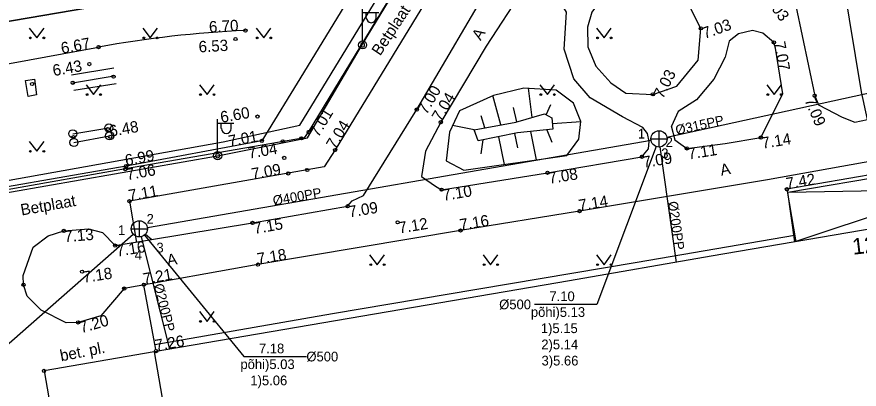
# Model space of a CAD drawing. Extents: x 473307 to 473719, y 6532843 to 6533381.
# Drawn here: x 473532 to 473584, y 6533003.3 to 6533026.3 of the extents above; entities that cross this region are included whole.
import ezdxf

# ---------------------------------------------------------------- set-up
doc = ezdxf.new("R2010")
doc.units = 0
for name, color, linetype in [('AED', 7, 'Continuous'), ('Default', 7, 'Continuous'), ('HALJASTUS', 7, 'Continuous'), ('HOONE', 7, 'Continuous'), ('HOONEDET', 7, 'Continuous'), ('KORGUS', 7, 'Continuous'), ('KPKAABEL', 7, 'Continuous'), ('MPKAABEL', 7, 'Continuous'), ('PIIR', 7, 'Continuous'), ('POST', 7, 'Continuous'), ('RAJATIS', 7, 'Continuous'), ('RELJEEF', 7, 'Continuous'), ('SKKAEV', 7, 'Continuous'), ('SKKAEV_NR', 7, 'Continuous'), ('SKTRASS', 7, 'Continuous'), ('SKTRASS_TEKST', 7, 'Continuous'), ('TEE', 7, 'Continuous')]:
    doc.layers.add(name, color=color, linetype=linetype)

# ---------------------------------------------------------------- blocks, each defined once
blk = doc.blocks.new('MURU')
at = {"layer": 'Default'}
for p, q in [((-0.93, 1.21), (0, 0)), ((0, 0), (0.89, 1.21))]:
    blk.add_line(p, q, dxfattribs=at)
for centre in [(-0.8, 0), (0.86, 0)]:
    blk.add_circle(centre, 0.11, dxfattribs=at)
blk = doc.blocks.new('PUPOST')
at = {"layer": 'Default'}
blk.add_circle((0, 0), 0.5, dxfattribs=at)
blk = doc.blocks.new('MEPOST')
at = {"layer": 'Default'}
blk.add_circle((0, 0), 0.5, dxfattribs=at)
for start, end in [(0, 180), (180, 0)]:
    blk.add_arc((0, 0), 0.25, start, end, dxfattribs=at)
blk = doc.blocks.new('VAPOST')
at = {"layer": 'Default'}
for p, q in [((0, 0.5), (0, 4.5)), ((0, 4), (2, 4)), ((0.45, 3.36), (0.45, 4)), ((1.68, 3.36), (1.68, 4))]:
    blk.add_line(p, q, dxfattribs=at)
blk.add_arc((1.07, 3.36), 0.613, 180, 0, dxfattribs=at)
blk = doc.blocks.new('KAKAEV')
at = {"layer": 'Default'}
for p, q in [((-1, 0), (1, 0)), ((0, -1), (0, 1))]:
    blk.add_line(p, q, dxfattribs=at)
blk.add_circle((0, 0), 1, dxfattribs=at)

msp = doc.modelspace()

# ---------------------------------------------------------------- linework, layer by layer
at = {"layer": 'AED'}
msp.add_lwpolyline([(473572.372, 6533059.989), (473562.796, 6533044.25), (473549.715, 6533022.819), (473547.153, 6533018.61), (473538.777, 6533017.059), (473515.614, 6533013.019), (473502.84, 6533010.765), (473486.499, 6533007.9), (473486.322, 6533008.043), (473484.734, 6533009.635), (473455.331, 6533045.745), (473429.609, 6533087.699), (473409.64, 6533128.98), (473398.626, 6533166.806)], dxfattribs=at)
at = {"layer": 'HALJASTUS'}
msp.add_lwpolyline([(473523.113, 6533015.835), (473521.816, 6533021.592), (473537.083, 6533024.398)], dxfattribs=at)
msp.add_arc((473549, 6532959.562), 65.922, 92.48527, 100.41445, dxfattribs=at)
at = {"layer": 'HOONE'}
for points in [[(473580.042, 6533012.374), (473579.602, 6533015.453), (473599.285, 6533018.774)], [(473599.285, 6533018.774), (473580.042, 6533012.374)], [(473579.602, 6533015.453), (473599.989, 6533015.81)]]:
    msp.add_lwpolyline(points, dxfattribs=at)
msp.add_lwpolyline([(473585.831, 6533013.369), (473574.881, 6533011.486), (473566.132, 6533009.962), (473540.511, 6533005.576), (473543.395, 6532988.91), (473585.455, 6532976.623), (473588.828, 6532956.753), (473587.886, 6532956.595), (473589.164, 6532949.286), (473629.221, 6532956.166), (473626.335, 6532972.834), (473619.836, 6532974.765), (473602.305, 6532979.874), (473597.625, 6532979.18), (473590.334, 6532981.418), (473586.157, 6533005.917), (473587.084, 6533006.076)], close=True, dxfattribs=at)
at = {"layer": 'HOONEDET'}
msp.add_lwpolyline([(473540.509, 6533005.59), (473533.715, 6533004.411), (473535.999, 6532991.198), (473543.379, 6532989.006)], dxfattribs=at)
at = {"layer": 'KORGUS'}
for centre in [(473574.239, 6533025.558), (473546.141, 6533025.422), (473545.529, 6533024.899), (473578.745, 6533024.687), (473537.083, 6533024.398), (473536.513, 6533023.351), (473538.004, 6533022.577), (473532.977, 6533022.124), (473535.49, 6533022.201), (473571.272, 6533021.483), (473581.265, 6533021.395), (473556.713, 6533020.545), (473546.887, 6533020.114), (473537.653, 6533019.344), (473558.193, 6533019.759), (473535.53, 6533018.837), (473537.802, 6533018.86), (473549.604, 6533018.77), (473550.041, 6533019.154), (473577.938, 6533018.813), (473547.153, 6533018.61), (473548.443, 6533018.58), (473551.671, 6533018.048), (473573.376, 6533018.143), (473548.538, 6533017.561), (473570.602, 6533017.631), (473538.726, 6533016.871), (473538.777, 6533017.059), (473549.953, 6533016.813), (473548.78, 6533016.602), (473564.78, 6533016.645), (473558.247, 6533015.597), (473579.55, 6533015.627), (473538.987, 6533014.888), (473552.448, 6533014.574), (473566.756, 6533014.277), (473555.533, 6533013.583), (473534.935, 6533013.053), (473546.585, 6533013.544), (473559.414, 6533013.077), (473538.104, 6533012.148), (473546.916, 6533010.975), (473536.058, 6533010.536), (473532.448, 6533009.73), (473538.663, 6533009.49), (473539.88, 6533009.732), (473535.82, 6533007.404), (473540.628, 6533005.633), (473533.715, 6533004.411)]:
    msp.add_circle(centre, 0.1, dxfattribs=at)
at = {"layer": 'KPKAABEL'}
msp.add_lwpolyline([(473495.73, 6532998.121), (473498.407, 6533003.379), (473503.632, 6533009.182), (473506.507, 6533009.537), (473509.619, 6533010.052), (473512.488, 6533010.976), (473514.601, 6533011.91), (473515.942, 6533013.381), (473544.763, 6533018.559), (473549.505, 6533019.588), (473569.283, 6533052.043), (473570.889, 6533054.575), (473571.863, 6533055.605), (473572.956, 6533056.611), (473574.847, 6533057.468), (473575.894, 6533057.765), (473578.381, 6533058.268)], dxfattribs=at)
at = {"layer": 'MPKAABEL'}
msp.add_lwpolyline([(473501.9, 6533010.247), (473503.599, 6533009.473), (473509.407, 6533010.303), (473514.158, 6533011.944), (473514.882, 6533012.941), (473529.573, 6533015.086), (473544.413, 6533017.683), (473549.969, 6533018.802), (473553.371, 6533024.572), (473561.183, 6533037.449), (473569.11, 6533050.338), (473570.373, 6533053.16), (473572.968, 6533056.378), (473576.022, 6533057.174), (473577.298, 6533057.025), (473577.882, 6533057.546), (473591.171, 6533059.946)], dxfattribs=at)
for points in [[(473557.128, 6533166.896), (473557.202, 6533167.153), (473557.17, 6533167.374), (473557.049, 6533167.727), (473556.952, 6533168.034), (473556.879, 6533168.251), (473556.724, 6533168.7), (473555.529, 6533172.103), (473554.018, 6533176.143), (473551.965, 6533180.794), (473542.001, 6533194.467), (473528.815, 6533203.479), (473521.877, 6533205.787), (473521.549, 6533205.862), (473521.332, 6533205.91), (473521.125, 6533205.955), (473520.94, 6533205.994), (473520.783, 6533206.026), (473520.617, 6533205.983), (473520.549, 6533205.81), (473520.512, 6533205.71), (473520.33, 6533205.301), (473520.277, 6533205.676), (473520.247, 6533205.87), (473520.186, 6533205.982), (473520.155, 6533206.063), (473520.032, 6533206.188), (473519.647, 6533206.25), (473519.297, 6533206.303), (473518.91, 6533206.37), (473518.338, 6533206.457), (473517.785, 6533206.534), (473517.113, 6533206.617), (473504.722, 6533206.361), (473489.125, 6533201.073), (473481.589, 6533195.708), (473477.331, 6533191.94), (473475.034, 6533189.807), (473474.489, 6533189.292), (473474.068, 6533188.932), (473473.832, 6533188.684), (473473.679, 6533188.468), (473473.566, 6533188.217), (473473.476, 6533188.304), (473473.306, 6533188.406), (473473.134, 6533188.531), (473472.969, 6533188.652), (473471.778, 6533189.567), (473469.957, 6533190.966), (473467.155, 6533193.119), (473463.064, 6533196.262), (473458.646, 6533199.657), (473454.573, 6533202.786), (473453.666, 6533203.482), (473453.293, 6533203.769), (473452.995, 6533203.998), (473452.474, 6533204.222), (473452.213, 6533204.228), (473451.967, 6533204.234), (473451.474, 6533204.245), (473450.255, 6533204.273), (473449.394, 6533204.293), (473448.978, 6533204.302), (473448.578, 6533204.312), (473448.301, 6533204.318), (473447.638, 6533204.311), (473446.313, 6533204.297), (473445.312, 6533204.286), (473443.932, 6533204.272), (473441.622, 6533204.247), (473436.282, 6533204.191), (473430.619, 6533203.804), (473423.016, 6533203.284), (473416.174, 6533202.8), (473411.7, 6533202.424), (473406.989, 6533202.027), (473406.298, 6533201.969), (473405.901, 6533201.936), (473405.663, 6533201.916), (473405.247, 6533201.618), (473405.511, 6533201.478), (473405.706, 6533201.471), (473405.859, 6533201.485), (473406.073, 6533201.505), (473406.3, 6533201.526), (473406.699, 6533201.563), (473407.182, 6533201.607), (473407.617, 6533201.647), (473410.794, 6533201.939), (473414.597, 6533202.289), (473416.16, 6533202.433), (473416.748, 6533202.487), (473416.992, 6533202.509), (473417.116, 6533202.479), (473417.282, 6533202.408), (473417.308, 6533202.242), (473417.347, 6533201.989), (473417.396, 6533201.677), (473417.449, 6533201.337), (473417.509, 6533200.949), (473418.04, 6533197.53), (473418.813, 6533192.552), (473421.708, 6533179.543), (473422.341, 6533175.512), (473423.507, 6533169.632), (473424, 6533167.141), (473424.184, 6533166.215), (473424.244, 6533165.909), (473424.294, 6533165.662), (473424.314, 6533165.561), (473424.105, 6533164.865), (473423.816, 6533164.809), (473423.525, 6533164.753), (473422.668, 6533164.588), (473418.846, 6533164.247), (473414.425, 6533164.061), (473411.47, 6533164.651), (473411.357, 6533164.673), (473410.881, 6533164.787), (473410.433, 6533164.888), (473409.953, 6533164.731), (473409.752, 6533164.287), (473409.631, 6533163.669), (473409.502, 6533157.703), (473410.074, 6533152.735), (473410.969, 6533148.729), (473415.098, 6533136.501), (473416.702, 6533131.364), (473421.711, 6533117.606), (473423.352, 6533113.701), (473430.005, 6533097.933), (473437.623, 6533088.588), (473441.02, 6533084.73), (473450.501, 6533069.242), (473457.775, 6533058.053), (473462.215, 6533052.558), (473465.73, 6533047.735), (473467.401, 6533046.054), (473469.034, 6533044.411), (473472.353, 6533043.145), (473481.411, 6533040.582), (473489.023, 6533038.632), (473491.007, 6533038.103), (473491.686, 6533037.936), (473492.014, 6533037.852), (473492.476, 6533037.76), (473492.806, 6533038.095), (473492.829, 6533038.485), (473492.856, 6533039.18), (473492.795, 6533042.335), (473492.716, 6533044.024), (473492.683, 6533044.743), (473492.671, 6533044.987), (473492.823, 6533045.601), (473492.984, 6533045.289), (473492.985, 6533045.105), (473493.028, 6533044.585), (473493.105, 6533042.767), (473493.222, 6533039.506), (473493.206, 6533038.15), (473493.196, 6533038.01), (473493.2, 6533037.815), (473493.516, 6533037.437), (473493.94, 6533037.314), (473494.338, 6533037.204), (473496.451, 6533036.58), (473497.497, 6533036.067), (473498.11, 6533035.695), (473498.481, 6533035.454), (473498.784, 6533035.294), (473499.155, 6533035.524), (473499.568, 6533035.786), (473499.965, 6533035.642), (473500.381, 6533035.468), (473500.664, 6533035.366), (473501.255, 6533035.156), (473502.131, 6533034.826), (473503.015, 6533034.496), (473504.909, 6533033.785), (473507.281, 6533033.099), (473509.703, 6533032.392), (473510.465, 6533032.171), (473510.886, 6533032.05), (473511.297, 6533031.932), (473511.665, 6533031.668), (473511.711, 6533031.312), (473511.692, 6533030.835), (473511.632, 6533029.982), (473511.533, 6533028.937), (473511.486, 6533028.283), (473511.407, 6533027.141), (473511.358, 6533026.503), (473511.358, 6533025.257), (473511.617, 6533023.934), (473511.536, 6533023.5), (473511.414, 6533022.901), (473511.43, 6533022.205), (473511.677, 6533020.728), (473511.888, 6533019.916), (473512.37, 6533017.914), (473512.52, 6533015.831), (473512.626, 6533013.709), (473512.595, 6533013.242), (473512.387, 6533012.718), (473557.128, 6533166.896), (473512.387, 6533012.718)], [(473512.387, 6533012.718), (473512.14, 6533013.652), (473512.045, 6533014.576), (473511.893, 6533017.504), (473511.641, 6533020.088), (473510.983, 6533025.715), (473511.056, 6533027.858), (473511.151, 6533031.477), (473511.114, 6533032.272), (473511.145, 6533032.474), (473511.13, 6533032.676), (473511.387, 6533032.849), (473511.704, 6533032.795), (473512.447, 6533032.669), (473513.158, 6533032.549), (473521.646, 6533031.115), (473533.63, 6533031.671), (473544.818, 6533035.685), (473553.6, 6533041.447), (473561.05, 6533049.393), (473566.522, 6533058.626), (473569.406, 6533068.153), (473570.207, 6533076.042), (473569.969, 6533079.529), (473569.868, 6533081.004), (473569.837, 6533081.466), (473569.791, 6533082.128), (473569.772, 6533082.416), (473569.894, 6533082.766), (473570.212, 6533082.86), (473570.72, 6533082.967), (473571.674, 6533083.167), (473572.589, 6533083.75), (473512.387, 6533012.718), (473572.589, 6533083.75)]]:
    msp.add_open_spline(points, degree=3, dxfattribs=at)
at = {"layer": 'PIIR'}
for points in [[(473383.26, 6533220.83), (473372.23, 6533259.41), (473496.37, 6533266.79), (473499.84, 6533206.38), (473559.2, 6533209.37), (473561.43, 6533165.2), (473601.75, 6533167.04), (473607.56, 6533132.38), (473611.09, 6533109.85), (473618.6, 6533063.82), (473572.63, 6533056.43), (473548.5, 6533028.91), (473478.82, 6533017), (473455.33, 6533045.76), (473432.18, 6533083.36), (473429.59, 6533087.74), (473409.64, 6533129), (473385.1, 6533214.25), (473398.68, 6533216.8), (473398.11, 6533224.3)], [(473486.57, 6533007.64), (473478.82, 6533017), (473548.5, 6533028.91), (473572.63, 6533056.43), (473618.6, 6533063.82), (473630.89, 6533065.72), (473654.16, 6532926.37), (473652.82, 6532924.82), (473637.7, 6532924.6), (473625.07, 6532926.73), (473607.63, 6532930.98), (473579.04, 6532941.93), (473554.34, 6532955.84), (473531.51, 6532970.21), (473509.62, 6532987.09)]]:
    msp.add_lwpolyline(points, close=True, dxfattribs=at)
at = {"layer": 'RAJATIS'}
for points in [[(473535.41, 6533022.692), (473538.015, 6533023.115)], [(473538.047, 6533022.609), (473535.47, 6533022.178)], [(473535.548, 6533021.734), (473538.161, 6533022.155)], [(473535.49, 6533019.051), (473537.715, 6533019.409)], [(473535.559, 6533018.51), (473537.761, 6533018.923)]]:
    msp.add_lwpolyline(points, dxfattribs=at)
msp.add_lwpolyline([(473532.578, 6533022.348), (473533.123, 6533022.429), (473533.254, 6533021.448), (473532.731, 6533021.347)], close=True, dxfattribs=at)
at = {"layer": 'RELJEEF'}
for p, q in [((473563.841, 6533020.055), (473563.605, 6533021.855)), ((473561.898, 6533019.592), (473561.406, 6533021.408)), ((473562.88, 6533019.779), (473562.676, 6533020.67)), ((473564.692, 6533020.227), (473564.975, 6533020.855)), ((473560.914, 6533019.41), (473560.681, 6533020.154)), ((473560.253, 6533019.287), (473558.926, 6533019.55)), ((473565.084, 6533019.686), (473566.827, 6533019.802)), ((473561.764, 6533018.869), (473562.11, 6533017.156)), ((473562.744, 6533019.067), (473562.923, 6533018.181)), ((473563.736, 6533019.191), (473564.081, 6533017.433)), ((473564.73, 6533019.298), (473565.05, 6533018.525)), ((473560.784, 6533018.671), (473560.665, 6533017.817))]:
    msp.add_line(p, q, dxfattribs=at)
for points in [[(473565.977, 6533017.699), (473566.706, 6533018.719), (473566.826, 6533019.806), (473566.384, 6533020.944), (473565.316, 6533021.737), (473563.325, 6533021.874), (473561.454, 6533021.42), (473559.357, 6533020.463), (473558.737, 6533019.149), (473558.521, 6533017.385), (473559.617, 6533016.806)], [(473560.253, 6533019.287), (473562.828, 6533019.764), (473564.604, 6533020.275), (473565.052, 6533020.032), (473565.117, 6533019.339), (473562.925, 6533019.104), (473560.508, 6533018.615)]]:
    msp.add_lwpolyline(points, close=True, dxfattribs=at)
at = {"layer": 'SKKAEV_NR'}
for points in [[(473571.485, 6533018.263), (473567.825, 6533008.515), (473563.97, 6533008.515)], [(473539.916, 6533012.793), (473546.048, 6533005.294), (473549.903, 6533005.294)]]:
    msp.add_lwpolyline(points, dxfattribs=at)
at = {"layer": 'SKTRASS'}
for points in [[(473572.149, 6533018.838), (473589.143, 6533022.555)], [(473540.092, 6533013.265), (473571.168, 6533018.646)], [(473572.741, 6533011.106), (473571.731, 6533018.236)], [(473512.824, 6532989.657), (473539.223, 6533012.85)], [(473541.487, 6533005.743), (473539.722, 6533012.695)], [(473539.981, 6533012.857), (473540.369, 6533012.53)]]:
    msp.add_lwpolyline(points, dxfattribs=at)
at = {"layer": 'TEE'}
for points in [[(473549.782, 6533018.805), (473550.041, 6533019.154), (473555.842, 6533028.725), (473562.083, 6533038.98), (473568.14, 6533048.878), (473572.72, 6533056.409), (473573.151, 6533056.476), (473572.511, 6533060.013)], [(473584.525, 6533019.936), (473584.149, 6533021.64), (473582.327, 6533032.76), (473579.699, 6533037.965), (473575.769, 6533043.341), (473573.951, 6533054.606), (473567.843, 6533044.573), (473562.514, 6533035.841), (473557.652, 6533027.859), (473551.671, 6533018.048), (473551.004, 6533017.017)], [(473585.125, 6533017.41), (473578.353, 6533016.212), (473566.756, 6533014.277), (473559.414, 6533013.077), (473546.916, 6533010.975), (473538.663, 6533009.49), (473537.225, 6533007.807), (473535.82, 6533007.404), (473535.073, 6533007.379), (473533.532, 6533008.162), (473532.677, 6533009.026), (473532.448, 6533009.73), (473532.426, 6533010.305), (473533.04, 6533012.04), (473533.977, 6533012.751), (473534.935, 6533013.053), (473536.468, 6533013.179), (473537.314, 6533012.951), (473538.104, 6533012.148), (473546.585, 6533013.544), (473552.448, 6533014.574), (473552.729, 6533014.913), (473553.427, 6533015.24), (473556.713, 6533020.545), (473561.672, 6533029.001)], [(473579.709, 6533028.824), (473581.265, 6533021.395), (473581.504, 6533020.838), (473582.968, 6533020.077), (473583.745, 6533019.767), (473584.525, 6533019.936)], [(473549.782, 6533018.805), (473538.736, 6533016.885), (473486.74, 6533007.668)], [(473551.004, 6533017.017), (473538.997, 6533014.882), (473539.421, 6533012.342)], [(473585.814, 6533013.366), (473585.294, 6533016.611), (473579.55, 6533015.627), (473580.094, 6533012.382)], [(473540.558, 6533006.033), (473551.513, 6533007.955), (473560.42, 6533009.446), (473570.303, 6533011.126), (473580.026, 6533012.786)], [(473540.613, 6533005.735), (473539.875, 6533009.708)]]:
    msp.add_lwpolyline(points, dxfattribs=at)
for points in [[(473567.524, 6533026.551), (473567.257, 6533025.636), (473567.273, 6533024.416), (473567.764, 6533023.221), (473568.692, 6533022.199), (473569.62, 6533021.548), (473571.272, 6533021.483), (473572.764, 6533021.999), (473574.074, 6533023.59), (473574.239, 6533025.558), (473573.315, 6533027.394), (473571.785, 6533028.349), (473570.699, 6533028.512), (473569.383, 6533028.229), (473567.746, 6533026.862)], [(473558.247, 6533015.597), (473564.78, 6533016.645), (473570.602, 6533017.631), (473571.019, 6533018.124), (473571.051, 6533018.564), (473570.955, 6533019.059), (473570.668, 6533019.443), (473569.403, 6533020.093), (473567.41, 6533021.272), (473566.399, 6533022.446), (473565.815, 6533024.266), (473565.954, 6533026.551), (473565.528, 6533027.251), (473563.718, 6533028.139), (473563.277, 6533027.983), (473560.994, 6533024.459), (473558.193, 6533019.759), (473557.253, 6533017.977), (473557, 6533016.405), (473557.864, 6533015.817)], [(473572.413, 6533019.537), (473572.641, 6533018.68), (473573.376, 6533018.143), (473575.735, 6533018.439), (473577.938, 6533018.813), (473579.289, 6533021.513), (473578.845, 6533024.341), (473578.745, 6533024.687), (473578.064, 6533025.269), (473577.421, 6533025.432), (473576.56, 6533025.214), (473575.985, 6533024.777), (473575.743, 6533023.77), (473575.049, 6533022.416), (473573.981, 6533021.136), (473572.842, 6533020.418), (473572.427, 6533019.526)]]:
    msp.add_lwpolyline(points, close=True, dxfattribs=at)

# ---------------------------------------------------------------- block references
at = {"layer": 'HALJASTUS', "xscale": 0.5, "yscale": 0.5}
for p in [(473533.271, 6533024.967), (473540.271, 6533024.967), (473547.271, 6533024.967), (473568.271, 6533024.967), (473536.771, 6533021.467), (473543.771, 6533021.467), (473564.771, 6533021.467), (473578.771, 6533021.467), (473533.271, 6533017.967), (473554.271, 6533010.967), (473561.271, 6533010.967), (473568.271, 6533010.967), (473543.771, 6533007.467)]:
    msp.add_blockref('MURU', p, dxfattribs=at)
at = {"layer": 'POST', "xscale": 0.5, "yscale": 0.5}
for name, p in [('VAPOST', (473553.37, 6533024.535)), ('MEPOST', (473553.37, 6533024.535)), ('VAPOST', (473544.427, 6533017.696)), ('MEPOST', (473544.427, 6533017.696))]:
    msp.add_blockref(name, p, dxfattribs=at)
at = {"layer": 'RAJATIS', "xscale": 0.5, "yscale": 0.5}
for p in [(473537.715, 6533019.409), (473535.49, 6533019.051), (473537.761, 6533018.923), (473535.559, 6533018.51)]:
    msp.add_blockref('PUPOST', p, dxfattribs=at)
at = {"layer": 'SKKAEV', "xscale": 0.5, "yscale": 0.5}
for p in [(473571.661, 6533018.731), (473539.599, 6533013.18)]:
    msp.add_blockref('KAKAEV', p, dxfattribs=at)

# ---------------------------------------------------------------- texts
at = {"layer": 'HOONE'}
msp.add_text('12', height=1, rotation=6.4003, dxfattribs=at).set_placement((473583.636, 6533011.58))
at = {"layer": 'KORGUS'}
for s, rotation, p in [('7.03', 306.4846, (473578.104, 6533027.393)), ('6.70', 3.2653, (473543.911, 6533025.295)), ('7.03', 19.6624, (473574.475, 6533024.899)), ('6.67', 10.4145, (473534.821, 6533023.982)), ('6.53', 3.2653, (473543.273, 6533024.069)), ('7.07', 280.3631, (473578.745, 6533024.687)), ('6.43', 10, (473534.309, 6533022.607)), ('7.03', 62.8208, (473571.895, 6533021.163)), ('7.00', 59.6098, (473557.317, 6533020.191)), ('7.04', 59.2088, (473558.193, 6533019.759)), ('7.09', 293.2234, (473580.622, 6533021.119)), ('6.60', 10, (473544.655, 6533019.72)), ('7.01', 58.7807, (473550.64, 6533018.791)), ('6.48', 10, (473537.802, 6533018.86)), ('7.04', 58.6295, (473551.671, 6533018.048)), ('7.01', 10.4907, (473545.154, 6533018.24)), ('7.14', 9.2803, (473578.051, 6533018.122)), ('7.04', 9.8821, (473546.363, 6533017.507)), ('7.11', 9.2803, (473573.489, 6533017.452)), ('6.99', 10.4907, (473538.777, 6533017.059)), ('7.09', 9.2803, (473570.715, 6533016.94)), ('7.06', 10.0964, (473538.849, 6533016.182)), ('7.09', 9.9275, (473546.58, 6533016.217)), ('7.08', 9.2803, (473564.893, 6533015.954)), ('7.42', 9.2803, (473579.55, 6533015.627)), ('7.11', 9.9275, (473538.987, 6533014.888)), ('7.10', 9.2803, (473558.36, 6533014.906)), ('7.14', 9.2803, (473566.756, 6533014.277)), ('7.09', 9.2803, (473552.561, 6533013.883)), ('7.15', 9.9597, (473546.706, 6533012.855)), ('7.12', 9.2803, (473555.646, 6533012.892)), ('7.16', 9.2803, (473559.414, 6533013.077)), ('7.13', 4.6987, (473534.992, 6533012.355)), ('7.16', 9.3436, (473538.218, 6533011.457)), ('7.18', 9.5478, (473546.916, 6533010.975)), ('7.18', 8.602, (473536.163, 6533009.844)), ('7.21', 10.203, (473539.88, 6533009.732)), ('7.20', 15.9945, (473536.013, 6533006.731)), ('7.26', 9.7134, (473540.622, 6533005.631))]:
    msp.add_text(s, height=0.7, rotation=rotation, dxfattribs=at).set_placement(p)
at = {"layer": 'SKKAEV_NR'}
for s, p in [('1', (473570.355, 6533018.755)), ('2', (473572.069, 6533018.237)), ('3', (473571.798, 6533017.543)), ('2', (473540.042, 6533013.497)), ('1', (473538.281, 6533012.798)), ('3', (473540.651, 6533011.721)), ('4', (473539.307, 6533011.273)), ('7.10', (473564.897, 6533008.715)), ('%%C500', (473561.798, 6533008.215)), ('põhi)5.13', (473563.754, 6533007.743)), ('1)5.15', (473564.369, 6533006.743)), ('7.18', (473546.976, 6533005.494)), ('2)5.14', (473564.397, 6533005.743)), ('%%C500', (473549.903, 6533004.994)), ('3)5.66', (473564.411, 6533004.743)), ('põhi)5.03', (473545.833, 6533004.522)), ('1)5.06', (473546.447, 6533003.522))]:
    msp.add_text(s, height=0.6, dxfattribs=at).set_placement(p)
at = {"layer": 'SKTRASS_TEKST'}
for s, rotation, p in [('%%C315PP', 12.3393, (473572.746, 6533018.968)), ('%%C400PP', 9.8224, (473547.886, 6533014.615)), ('%%C200PP', 278.0617, (473572.212, 6533014.84)), ('%%C200PP', 284.2428, (473540.478, 6533009.718))]:
    msp.add_text(s, height=0.6, rotation=rotation, dxfattribs=at).set_placement(p)
at = {"layer": 'TEE'}
for s, rotation, p in [('Betplaat', 56.5299, (473554.454, 6533023.821)), ('A', 58.0169, (473560.649, 6533024.767)), ('A', 10.8704, (473575.503, 6533016.456)), ('Betplaat', 10.0777, (473532.334, 6533014)), ('A', 9.8051, (473541.355, 6533010.893)), ('bet. pl.', 11.0454, (473534.772, 6533004.996))]:
    msp.add_text(s, height=0.7, rotation=rotation, dxfattribs=at).set_placement(p)

doc.saveas('drawing.dxf')
